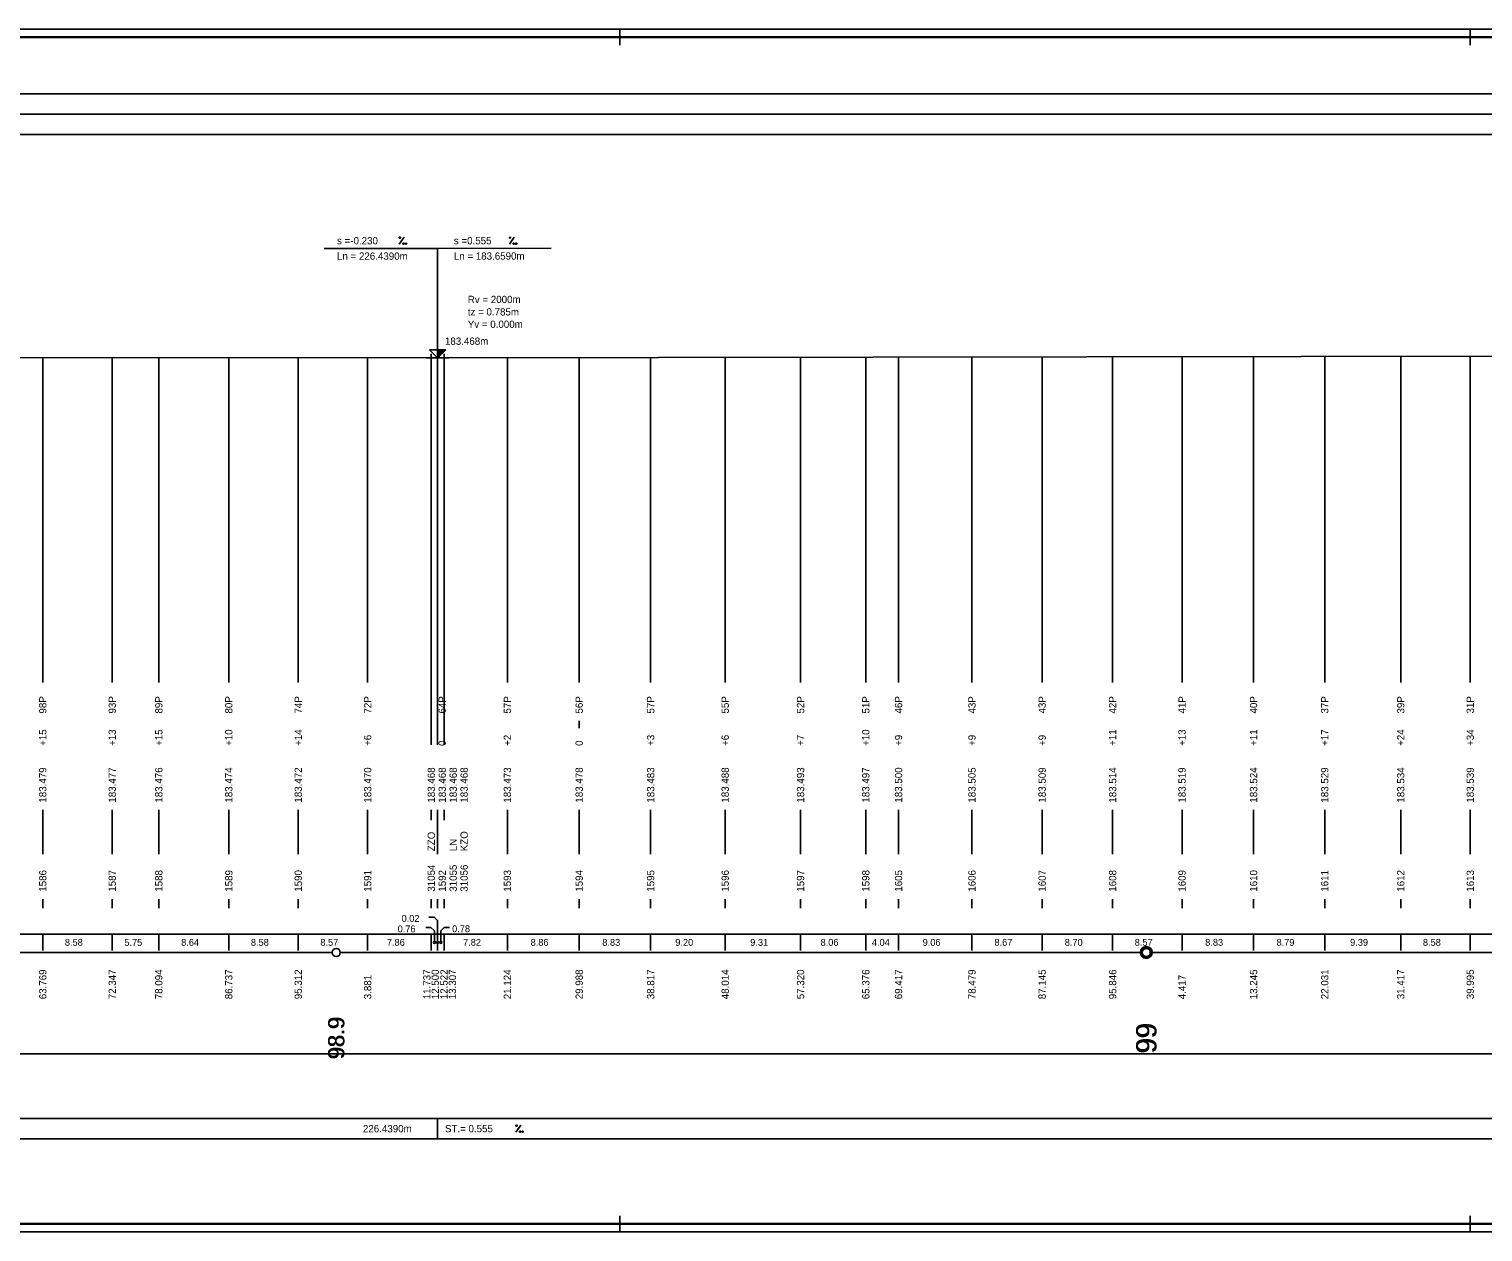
# Model space of a CAD drawing. Extents: x 0 to 10087, y -805 to 297.
# Drawn here: x 5104.2 to 5463.1, y 0 to 297 of the extents above; entities that cross this region are included whole.
import ezdxf

# ---------------------------------------------------------------- set-up
doc = ezdxf.new("R2010")
doc.units = 0
for name, color, linetype in [('CARKY_HODNOT', 7, 'Continuous'), ('KRIV1_CARA', 7, 'Continuous'), ('NIVELETA_CARA', 7, 'Continuous'), ('NIVELETA_TEXT', 7, 'Continuous'), ('RAM', 7, 'Continuous'), ('REZERVA', 7, 'Continuous'), ('STAN_CARA', 7, 'Continuous'), ('STAN_PAS', 7, 'Continuous'), ('STAN_TEXT', 7, 'Continuous'), ('TEXT', 7, 'Continuous'), ('TXT_C_BODU', 7, 'Continuous')]:
    doc.layers.add(name, color=color, linetype=linetype)

msp = doc.modelspace()

# ---------------------------------------------------------------- linework, layer by layer
at = {"layer": 'CARKY_HODNOT'}
for p, q in [((5107.54, 138.35), (5107.54, 215.9)), ((5124.69, 138.35), (5124.69, 215.89)), ((5136.19, 138.35), (5136.19, 215.88)), ((5153.47, 138.35), (5153.47, 215.87)), ((5170.62, 138.35), (5170.62, 215.86)), ((5187.76, 138.35), (5187.76, 215.85)), ((5203.47, 138.35), (5203.47, 215.84)), ((5205, 138.35), (5205, 215.84)), ((5205.04, 138.35), (5205.04, 215.84)), ((5206.61, 138.35), (5206.61, 215.84)), ((5222.25, 138.35), (5222.25, 215.86)), ((5239.98, 138.35), (5239.98, 215.89)), ((5257.63, 138.35), (5257.63, 215.91)), ((5276.03, 138.35), (5276.03, 215.94)), ((5294.64, 138.35), (5294.64, 215.96)), ((5310.75, 138.35), (5310.75, 215.99)), ((5318.83, 138.35), (5318.83, 216)), ((5336.96, 138.35), (5336.96, 216.02)), ((5354.29, 138.35), (5354.29, 216.05)), ((5371.69, 138.35), (5371.69, 216.07)), ((5388.83, 138.35), (5388.83, 216.1)), ((5406.49, 138.35), (5406.49, 216.12)), ((5424.06, 138.35), (5424.06, 216.14)), ((5442.83, 138.35), (5442.83, 216.17)), ((5459.99, 138.35), (5459.99, 216.19)), ((5107.54, 135.65), (5107.54, 138.35)), ((5124.69, 135.65), (5124.69, 138.35)), ((5136.19, 135.65), (5136.19, 138.35)), ((5153.47, 135.65), (5153.47, 138.35)), ((5170.62, 135.65), (5170.62, 138.35)), ((5187.76, 135.65), (5187.76, 138.35)), ((5203.47, 126.2), (5203.47, 138.35)), ((5205, 135.65), (5205, 138.35)), ((5205.04, 126.2), (5205.04, 138.35)), ((5206.61, 126.2), (5206.61, 138.35)), ((5222.25, 135.65), (5222.25, 138.35)), ((5239.98, 135.65), (5239.98, 138.35)), ((5257.63, 135.65), (5257.63, 138.35)), ((5276.03, 135.65), (5276.03, 138.35)), ((5294.64, 135.65), (5294.64, 138.35)), ((5310.75, 135.65), (5310.75, 138.35)), ((5318.83, 135.65), (5318.83, 138.35)), ((5336.96, 135.65), (5336.96, 138.35)), ((5354.29, 135.65), (5354.29, 138.35)), ((5371.69, 135.65), (5371.69, 138.35)), ((5388.83, 135.65), (5388.83, 138.35)), ((5406.49, 135.65), (5406.49, 138.35)), ((5424.06, 135.65), (5424.06, 138.35)), ((5442.83, 135.65), (5442.83, 138.35)), ((5459.99, 135.65), (5459.99, 138.35)), ((5203.47, 120.25), (5203.47, 126.2)), ((5205, 124.35), (5205, 126.2)), ((5205.04, 120.25), (5205.04, 126.2)), ((5206.61, 120.25), (5206.61, 126.2)), ((5239.98, 124.35), (5239.98, 126.2)), ((5107.54, 93.3), (5107.54, 104.2)), ((5124.69, 93.3), (5124.69, 104.2)), ((5136.19, 93.3), (5136.19, 104.2)), ((5153.47, 93.3), (5153.47, 104.2)), ((5170.62, 93.3), (5170.62, 104.2)), ((5187.76, 93.3), (5187.76, 104.2)), ((5203.47, 101.65), (5203.47, 104.2)), ((5205, 93.3), (5205, 104.2)), ((5205.04, 100), (5205.04, 104.2)), ((5206.61, 101.65), (5206.61, 104.2)), ((5222.25, 93.3), (5222.25, 104.2)), ((5239.98, 93.3), (5239.98, 104.2)), ((5257.63, 93.3), (5257.63, 104.2)), ((5276.03, 93.3), (5276.03, 104.2)), ((5294.64, 93.3), (5294.64, 104.2)), ((5310.75, 93.3), (5310.75, 104.2)), ((5318.83, 93.3), (5318.83, 104.2)), ((5336.96, 93.3), (5336.96, 104.2)), ((5354.29, 93.3), (5354.29, 104.2)), ((5371.69, 93.3), (5371.69, 104.2)), ((5388.83, 93.3), (5388.83, 104.2)), ((5406.49, 93.3), (5406.49, 104.2)), ((5424.06, 93.3), (5424.06, 104.2)), ((5442.83, 93.3), (5442.83, 104.2)), ((5459.99, 93.3), (5459.99, 104.2)), ((5107.54, 79.9), (5107.54, 82.2)), ((5124.69, 79.9), (5124.69, 82.2)), ((5136.19, 79.9), (5136.19, 82.2)), ((5153.47, 79.9), (5153.47, 82.2)), ((5170.62, 79.9), (5170.62, 82.2)), ((5187.76, 79.9), (5187.76, 82.2)), ((5203.47, 79.9), (5203.47, 82.2)), ((5205, 79.9), (5205, 82.2)), ((5205.04, 79.9), (5205.04, 82.2)), ((5206.61, 79.9), (5206.61, 82.2)), ((5222.25, 79.9), (5222.25, 82.2)), ((5239.98, 79.9), (5239.98, 82.2)), ((5257.63, 79.9), (5257.63, 82.2)), ((5276.03, 79.9), (5276.03, 82.2)), ((5294.64, 79.9), (5294.64, 82.2)), ((5310.75, 79.9), (5310.75, 82.2)), ((5318.83, 79.9), (5318.83, 82.2)), ((5336.96, 79.9), (5336.96, 82.2)), ((5354.29, 79.9), (5354.29, 82.2)), ((5371.69, 79.9), (5371.69, 82.2)), ((5388.83, 79.9), (5388.83, 82.2)), ((5406.49, 79.9), (5406.49, 82.2)), ((5424.06, 79.9), (5424.06, 82.2)), ((5442.83, 79.9), (5442.83, 82.2)), ((5459.99, 79.9), (5459.99, 82.2))]:
    msp.add_line(p, q, dxfattribs=at)
at = {"layer": 'KRIV1_CARA'}
msp.add_line((5093.47, 44), (6545.11, 44), dxfattribs=at)
at = {"layer": 'NIVELETA_CARA'}
for p, q in [((300, 281), (8321.33, 281)), ((300, 276), (8321.33, 276)), ((300, 271), (8321.33, 271)), ((5205.04, 242.84), (5177.04, 242.86)), ((5205.04, 242.84), (5233.04, 242.88)), ((5205.04, 215.84), (5205.04, 242.84)), ((4753.55, 216.1), (5203.47, 215.84)), ((5203.47, 215.84), (5202.24, 215.84)), ((5205.04, 215.84), (5203.04, 217.84)), ((5203.04, 217.84), (5207.04, 217.84)), ((5203.47, 215.84), (5203.47, 216.84)), ((5203.47, 215.84), (5205.04, 215.84)), ((5205.04, 215.84), (5205.04, 217.84)), ((5207.04, 217.84), (5205.04, 215.84)), ((5205.04, 215.84), (5206.61, 215.84)), ((5205.11, 215.91), (5205.11, 217.84)), ((5205.18, 215.97), (5205.18, 217.84)), ((5205.24, 216.04), (5205.24, 217.84)), ((5205.31, 216.11), (5205.31, 217.84)), ((5205.38, 216.17), (5205.38, 217.84)), ((5205.44, 216.24), (5205.44, 217.84)), ((5205.51, 216.31), (5205.51, 217.84)), ((5205.58, 216.37), (5205.58, 217.84)), ((5205.64, 216.44), (5205.64, 217.84)), ((5205.71, 216.51), (5205.71, 217.84)), ((5205.78, 216.57), (5205.78, 217.84)), ((5205.84, 216.64), (5205.84, 217.84)), ((5205.91, 216.71), (5205.91, 217.84)), ((5205.98, 216.77), (5205.98, 217.84)), ((5206.04, 216.84), (5206.04, 217.84)), ((5206.11, 216.91), (5206.11, 217.84)), ((5206.18, 216.97), (5206.18, 217.84)), ((5206.24, 217.04), (5206.24, 217.84)), ((5206.31, 217.11), (5206.31, 217.84)), ((5206.38, 217.17), (5206.38, 217.84)), ((5206.44, 217.24), (5206.44, 217.84)), ((5206.51, 217.31), (5206.51, 217.84)), ((5206.58, 217.37), (5206.58, 217.84)), ((5206.61, 215.84), (5206.61, 216.84)), ((5206.61, 215.84), (5568, 216.34)), ((5207.84, 215.84), (5206.61, 215.84)), ((5206.64, 217.44), (5206.64, 217.84)), ((5206.71, 217.51), (5206.71, 217.84)), ((5206.78, 217.57), (5206.78, 217.84)), ((5206.84, 217.64), (5206.84, 217.84)), ((5206.91, 217.71), (5206.91, 217.84)), ((5206.98, 217.77), (5206.98, 217.84)), ((500, 28), (8321.33, 28)), ((5205.04, 23), (5205.04, 28)), ((500, 23), (8321.33, 23))]:
    msp.add_line(p, q, dxfattribs=at)
at = {"layer": 'NIVELETA_TEXT'}
for p, q in [((5195.55, 243.85), (5196.74, 245.64)), ((5195.55, 245.64), (5195.55, 245.35)), ((5195.84, 245.64), (5195.55, 245.64)), ((5195.55, 245.64), (5195.55, 245.64)), ((5195.55, 245.35), (5195.84, 245.34)), ((5195.84, 245.34), (5195.84, 245.64)), ((5196.46, 244.14), (5196.46, 243.85)), ((5196.75, 244.14), (5196.46, 244.14)), ((5196.46, 244.14), (5196.46, 244.14)), ((5196.75, 243.85), (5196.75, 244.14)), ((5197.07, 244.14), (5197.07, 243.85)), ((5197.37, 244.14), (5197.07, 244.14)), ((5197.07, 244.14), (5197.07, 244.14)), ((5197.37, 243.85), (5197.37, 244.14)), ((5222.74, 245.66), (5222.74, 245.36)), ((5222.75, 245.66), (5222.74, 245.66)), ((5222.74, 245.36), (5223.04, 245.36)), ((5222.75, 243.87), (5223.93, 245.66)), ((5223.04, 245.66), (5222.75, 245.66)), ((5223.04, 245.36), (5223.04, 245.66)), ((5223.65, 244.17), (5223.66, 243.87)), ((5223.66, 244.17), (5223.65, 244.16)), ((5223.95, 244.17), (5223.66, 244.17)), ((5223.95, 243.87), (5223.95, 244.17)), ((5224.27, 244.17), (5224.27, 243.87)), ((5224.57, 244.17), (5224.27, 244.17)), ((5224.27, 244.17), (5224.27, 244.16)), ((5224.57, 243.87), (5224.57, 244.17)), ((5196.46, 243.85), (5196.75, 243.85)), ((5197.07, 243.85), (5197.37, 243.85)), ((5223.66, 243.87), (5223.95, 243.87)), ((5224.27, 243.87), (5224.57, 243.87)), ((5224.35, 24.6), (5225.54, 26.4)), ((5224.35, 26.4), (5224.35, 26.1)), ((5224.64, 26.4), (5224.35, 26.4)), ((5224.35, 26.4), (5224.35, 26.39)), ((5224.35, 26.1), (5224.64, 26.1)), ((5224.64, 26.1), (5224.64, 26.4)), ((5225.26, 24.9), (5225.26, 24.6)), ((5225.55, 24.9), (5225.26, 24.9)), ((5225.26, 24.9), (5225.26, 24.89)), ((5225.26, 24.6), (5225.55, 24.6)), ((5225.55, 24.6), (5225.55, 24.9)), ((5225.87, 24.9), (5225.87, 24.6)), ((5226.17, 24.9), (5225.87, 24.9)), ((5225.87, 24.9), (5225.87, 24.89)), ((5225.87, 24.6), (5226.17, 24.6)), ((5226.17, 24.6), (5226.17, 24.9))]:
    msp.add_line(p, q, dxfattribs=at)
at = {"layer": 'RAM'}
for p, q in [((8636.33, 297), (0, 297)), ((8634.33, 295.1), (2, 295.1)), ((8634.33, 295), (2, 295)), ((8634.33, 294.9), (2, 294.9)), ((5250, 293), (5250, 297)), ((5460, 293), (5460, 297)), ((5250, 0), (5250, 4)), ((5460, 0), (5460, 4)), ((0, 0), (8636.33, 0)), ((2, 2.1), (8634.33, 2.1)), ((2, 2), (8634.33, 2)), ((2, 1.9), (8634.33, 1.9))]:
    msp.add_line(p, q, dxfattribs=at)
at = {"layer": 'REZERVA'}
for centre, radius in [((5180, 69), 1), ((5380, 69), 1.45), ((5380, 69), 1.4), ((5380, 69), 1.35), ((5380, 69), 1.3), ((5380, 69), 1.25), ((5380, 69), 1.2), ((5380, 69), 1.15), ((5380, 69), 1.1), ((5380, 69), 1.05), ((5380, 69), 1)]:
    msp.add_circle(centre, radius, dxfattribs=at)
at = {"layer": 'STAN_CARA'}
for p, q in [((4981, 69), (5179, 69)), ((5181, 69), (5378.5, 69)), ((5381.5, 69), (5579, 69))]:
    msp.add_line(p, q, dxfattribs=at)
at = {"layer": 'STAN_PAS'}
for p, q in [((5204.17, 77.75), (5202.9, 77.75)), ((5205.02, 76.9), (5204.17, 77.75)), ((5205.02, 71.75), (5205.02, 76.9)), ((300, 73.5), (8321.33, 73.5)), ((5107.54, 69.5), (5107.54, 73.5)), ((5124.69, 69.5), (5124.69, 73.5)), ((5136.19, 69.5), (5136.19, 73.5)), ((5153.47, 69.5), (5153.47, 73.5)), ((5170.62, 69.5), (5170.62, 73.5)), ((5187.76, 69.5), (5187.76, 73.5)), ((5203.39, 75.2), (5202.11, 75.2)), ((5204.24, 74.35), (5203.39, 75.2)), ((5203.47, 69.5), (5203.47, 73.5)), ((5204.24, 71.75), (5204.24, 74.35)), ((5205, 69.5), (5205, 73.5)), ((5205.04, 69.5), (5205.04, 73.5)), ((5205.83, 74.35), (5206.68, 75.2)), ((5205.83, 71.75), (5205.83, 74.35)), ((5206.61, 69.5), (5206.61, 73.5)), ((5206.68, 75.2), (5207.95, 75.2)), ((5222.25, 69.5), (5222.25, 73.5)), ((5239.98, 69.5), (5239.98, 73.5)), ((5257.63, 69.5), (5257.63, 73.5)), ((5276.03, 69.5), (5276.03, 73.5)), ((5294.64, 69.5), (5294.64, 73.5)), ((5310.75, 69.5), (5310.75, 73.5)), ((5318.83, 69.5), (5318.83, 73.5)), ((5336.96, 69.5), (5336.96, 73.5)), ((5354.29, 69.5), (5354.29, 73.5)), ((5371.69, 69.5), (5371.69, 73.5)), ((5388.83, 69.5), (5388.83, 73.5)), ((5406.49, 69.5), (5406.49, 73.5)), ((5424.06, 69.5), (5424.06, 73.5)), ((5442.83, 69.5), (5442.83, 73.5)), ((5459.99, 69.5), (5459.99, 73.5))]:
    msp.add_line(p, q, dxfattribs=at)
for centre in [(5204.24, 71.5), (5205.02, 71.5), (5205.83, 71.5)]:
    msp.add_circle(centre, 0.25, dxfattribs=at)

# ---------------------------------------------------------------- texts
at = {"layer": 'NIVELETA_TEXT'}
for s, rotation, p in [('s =-0.230', 359.9671, (5180.19, 243.85)), ('s =0.555', 0.0796, (5209.04, 243.85)), ('Ln = 226.4390m', 359.9671, (5180.19, 240.05)), ('Ln = 183.6590m', 0.0796, (5209.04, 240.05))]:
    msp.add_text(s, height=1.8, rotation=rotation, dxfattribs=at).set_placement(p)
for s, p in [('Rv = 2000m', (5212.48, 229.34)), ('tz = 0.785m', (5212.48, 226.28)), ('Yv = 0.000m', (5212.48, 223.22)), ('183.468m', (5206.84, 219.04)), ('226.4390m', (5186.59, 24.6)), ('ST.= 0.555', (5206.84, 24.6))]:
    msp.add_text(s, height=1.8, dxfattribs=at).set_placement(p)
at = {"layer": 'STAN_TEXT'}
for s, p in [('0.76', (5195.16, 73.98)), ('0.02', (5196.13, 76.56)), ('0.78', (5208.61, 74.01)), ('8.58', (5113, 70.65)), ('5.75', (5127.68, 70.63)), ('8.64', (5141.71, 70.65)), ('8.58', (5158.93, 70.65)), ('8.57', (5176.08, 70.65)), ('7.86', (5192.5, 70.65)), ('7.82', (5211.31, 70.65)), ('8.86', (5228, 70.65)), ('8.83', (5245.69, 70.65)), ('9.20', (5263.71, 70.65)), ('9.31', (5282.22, 70.65)), ('8.06', (5299.58, 70.65)), ('4.04', (5312.25, 70.64)), ('9.06', (5324.78, 70.65)), ('8.67', (5342.51, 70.65)), ('8.70', (5359.87, 70.65)), ('8.57', (5377.15, 70.65)), ('8.83', (5394.55, 70.65)), ('8.79', (5412.16, 70.65)), ('9.39', (5430.33, 70.65)), ('8.58', (5448.3, 70.65))]:
    msp.add_text(s, height=1.7, dxfattribs=at).set_placement(p)
for s, height, p in [('63.769', 1.8, (5108.44, 57.45)), ('72.347', 1.8, (5125.59, 57.45)), ('78.094', 1.8, (5137.09, 57.45)), ('86.737', 1.8, (5154.37, 57.45)), ('95.312', 1.8, (5171.52, 57.45)), ('11.737', 1.8, (5203.27, 57.45)), ('12.500', 1.8, (5205.35, 57.45)), ('12.522', 1.8, (5207.5, 57.45)), ('13.307', 1.8, (5209.58, 57.45)), ('21.124', 1.8, (5223.15, 57.45)), ('29.988', 1.8, (5240.88, 57.45)), ('38.817', 1.8, (5258.53, 57.45)), ('48.014', 1.8, (5276.93, 57.45)), ('57.320', 1.8, (5295.54, 57.45)), ('65.376', 1.8, (5311.65, 57.45)), ('69.417', 1.8, (5319.73, 57.45)), ('78.479', 1.8, (5337.86, 57.45)), ('87.145', 1.8, (5355.19, 57.45)), ('95.846', 1.8, (5372.59, 57.45)), ('13.245', 1.8, (5407.39, 57.45)), ('22.031', 1.8, (5424.96, 57.45)), ('31.417', 1.8, (5443.73, 57.45)), ('39.995', 1.8, (5460.89, 57.45)), ('3.881', 1.8, (5188.66, 57.45)), ('4.417', 1.8, (5389.73, 57.45)), ('    98.9', 4, (5182, 36.84)), ('    98.9', 4, (5182, 36.74)), ('    98.9', 4, (5182, 36.64)), ('    99', 5, (5382.5, 36.8)), ('    99', 5, (5382.5, 36.7)), ('    99', 5, (5382.5, 36.6))]:
    msp.add_text(s, height=height, rotation=90, dxfattribs=at).set_placement(p)
at = {"layer": 'TEXT'}
for s, p in [('98P', (5108.44, 128)), ('93P', (5125.59, 128)), ('89P', (5137.09, 128)), ('80P', (5154.37, 128)), ('74P', (5171.52, 128)), ('72P', (5188.66, 128)), ('64P', (5207.07, 128)), ('57P', (5223.15, 128)), ('56P', (5240.88, 128)), ('57P', (5258.53, 128)), ('55P', (5276.93, 128)), ('52P', (5295.54, 128)), ('51P', (5311.65, 128)), ('46P', (5319.73, 128)), ('43P', (5337.86, 128)), ('43P', (5355.19, 128)), ('42P', (5372.59, 128)), ('41P', (5389.73, 128)), ('40P', (5407.39, 128)), ('37P', (5424.96, 128)), ('39P', (5443.73, 128)), ('31P', (5460.89, 128)), ('+15', (5108.44, 120)), ('+13', (5125.59, 120)), ('+15', (5137.09, 120)), ('+10', (5154.37, 120)), ('+14', (5171.52, 120)), ('+6', (5188.66, 120)), ('+2', (5223.15, 120)), ('+3', (5258.53, 120)), ('+6', (5276.93, 120)), ('+7', (5295.54, 120)), ('+10', (5311.65, 120)), ('+9', (5319.73, 120)), ('+9', (5337.86, 120)), ('+9', (5355.19, 120)), ('+11', (5372.59, 120)), ('+13', (5389.73, 120)), ('+11', (5407.39, 120)), ('+17', (5424.96, 120)), ('+24', (5443.73, 120)), ('+34', (5460.89, 120)), ('0', (5207.07, 120)), ('0', (5240.88, 120)), ('183.479', (5108.44, 106)), ('183.477', (5125.59, 106)), ('183.476', (5137.09, 106)), ('183.474', (5154.37, 106)), ('183.472', (5171.52, 106)), ('183.470', (5188.66, 106)), ('183.468', (5204.37, 106)), ('183.468', (5207.07, 106)), ('183.468', (5209.77, 106)), ('183.468', (5212.47, 106)), ('183.473', (5223.15, 106)), ('183.478', (5240.88, 106)), ('183.483', (5258.53, 106)), ('183.488', (5276.93, 106)), ('183.493', (5295.54, 106)), ('183.497', (5311.65, 106)), ('183.500', (5319.73, 106)), ('183.505', (5337.86, 106)), ('183.509', (5355.19, 106)), ('183.514', (5372.59, 106)), ('183.519', (5389.73, 106)), ('183.524', (5407.39, 106)), ('183.529', (5424.96, 106)), ('183.534', (5443.73, 106)), ('183.539', (5460.89, 106)), ('ZZO', (5204.37, 94)), ('KZO', (5212.47, 94)), ('LN', (5209.77, 94))]:
    msp.add_text(s, height=1.8, rotation=90, dxfattribs=at).set_placement(p)
at = {"layer": 'TXT_C_BODU'}
for s, p in [('31054', (5204.37, 84)), ('31055', (5209.77, 84)), ('31056', (5212.47, 84)), ('1586', (5108.44, 84)), ('1587', (5125.59, 84)), ('1588', (5137.09, 84)), ('1589', (5154.37, 84)), ('1590', (5171.52, 84)), ('1591', (5188.66, 84)), ('1592', (5207.07, 84)), ('1593', (5223.15, 84)), ('1594', (5240.88, 84)), ('1595', (5258.53, 84)), ('1596', (5276.93, 84)), ('1597', (5295.54, 84)), ('1598', (5311.65, 84)), ('1605', (5319.73, 84)), ('1606', (5337.86, 84)), ('1607', (5355.19, 84)), ('1608', (5372.59, 84)), ('1609', (5389.73, 84)), ('1610', (5407.39, 84)), ('1611', (5424.96, 84)), ('1612', (5443.73, 84)), ('1613', (5460.89, 84))]:
    msp.add_text(s, height=1.8, rotation=90, dxfattribs=at).set_placement(p)

doc.saveas('drawing.dxf')
